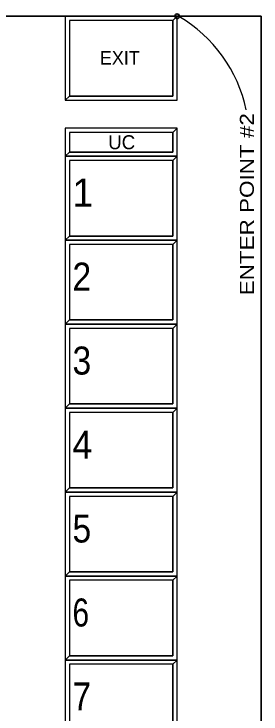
# Model space of a CAD drawing. Extents: x 95906.8 to 95923.6, y 90964.8 to 90972.8.
# Drawn here: x 95917.949 to 95918.832, y 90970.269 to 90972.77 of the extents above; entities that cross this region are included whole.
import ezdxf
from ezdxf.enums import TextEntityAlignment as Align

# ---------------------------------------------------------------- set-up
doc = ezdxf.new("R2010")
doc.units = 0
doc.header["$LTSCALE"] = 0.019
for name, color, linetype, lineweight in [('1', 7, 'Continuous', 25), ('11', 7, 'Continuous', 25), ('16', 7, 'Continuous', 25), ('18', 7, 'Continuous', 25), ('2', 7, 'Continuous', 13), ('3', 7, 'Continuous', 25), ('6', 7, 'Continuous', 35), ('7', 7, 'Continuous', 35)]:
    doc.layers.add(name, color=color, linetype=linetype, lineweight=lineweight)

msp = doc.modelspace()

# ---------------------------------------------------------------- linework, layer by layer
at = {"layer": '1'}
for points in [[(95918.1323, 90972.4617), (95918.5323, 90972.4617), (95918.5323, 90972.7617), (95918.1323, 90972.7617)], [(95918.1323, 90972.2617), (95918.5323, 90972.2617), (95918.5323, 90972.3617), (95918.1323, 90972.3617)], [(95918.1323, 90971.9617), (95918.5323, 90971.9617), (95918.5323, 90972.2617), (95918.1323, 90972.2617)], [(95918.1323, 90971.6617), (95918.5323, 90971.6617), (95918.5323, 90971.9617), (95918.1323, 90971.9617)], [(95918.1323, 90971.3617), (95918.5323, 90971.3617), (95918.5323, 90971.6617), (95918.1323, 90971.6617)], [(95918.1323, 90971.0617), (95918.5323, 90971.0617), (95918.5323, 90971.3617), (95918.1323, 90971.3617)], [(95918.1323, 90970.7617), (95918.5323, 90970.7617), (95918.5323, 90971.0617), (95918.1323, 90971.0617)], [(95918.1323, 90970.4617), (95918.5323, 90970.4617), (95918.5323, 90970.7617), (95918.1323, 90970.7617)], [(95918.1323, 90970.1617), (95918.5323, 90970.1617), (95918.5323, 90970.4617), (95918.1323, 90970.4617)]]:
    msp.add_lwpolyline(points, close=True, dxfattribs=at)
at = {"layer": '11'}
for points in [[(95918.1473, 90971.9767), (95918.5173, 90971.9767), (95918.5173, 90972.2467), (95918.1473, 90972.2467)], [(95918.1473, 90971.6767), (95918.5173, 90971.6767), (95918.5173, 90971.9467), (95918.1473, 90971.9467)], [(95918.1473, 90971.3767), (95918.5173, 90971.3767), (95918.5173, 90971.6467), (95918.1473, 90971.6467)], [(95918.1473, 90971.0767), (95918.5173, 90971.0767), (95918.5173, 90971.3467), (95918.1473, 90971.3467)], [(95918.1473, 90970.7767), (95918.5173, 90970.7767), (95918.5173, 90971.0467), (95918.1473, 90971.0467)], [(95918.1473, 90970.4767), (95918.5173, 90970.4767), (95918.5173, 90970.7467), (95918.1473, 90970.7467)], [(95918.1473, 90970.1767), (95918.5173, 90970.1767), (95918.5173, 90970.4467), (95918.1473, 90970.4467)]]:
    msp.add_lwpolyline(points, close=True, dxfattribs=at)
at = {"layer": '16'}
msp.add_lwpolyline([(95918.1473, 90972.4767), (95918.5173, 90972.4767), (95918.5173, 90972.7467), (95918.1473, 90972.7467)], close=True, dxfattribs=at)
msp.add_lwpolyline([(95918.1473, 90972.4767), (95918.5173, 90972.4767), (95918.5173, 90972.7467), (95918.1473, 90972.7467)], close=True, dxfattribs=at)
at = {"layer": '18'}
msp.add_lwpolyline([(95918.1473, 90972.2767), (95918.5173, 90972.2767), (95918.5173, 90972.3467), (95918.1473, 90972.3467)], close=True, dxfattribs=at)
at = {"layer": '2'}
for points in [[(95918.1323, 90972.7617), (95918.1323, 90972.4617), (95918.1473, 90972.4767), (95918.1473, 90972.7467), (95918.5173, 90972.7467), (95918.5323, 90972.7617)], [(95918.1323, 90972.3617), (95918.1323, 90972.2617), (95918.1473, 90972.2767), (95918.1473, 90972.3467), (95918.5173, 90972.3467), (95918.5323, 90972.3617)], [(95918.1323, 90972.2617), (95918.1323, 90971.9617), (95918.1473, 90971.9767), (95918.1473, 90972.2467), (95918.5173, 90972.2467), (95918.5323, 90972.2617)], [(95918.1323, 90971.9617), (95918.1323, 90971.6617), (95918.1473, 90971.6767), (95918.1473, 90971.9467), (95918.5173, 90971.9467), (95918.5323, 90971.9617)], [(95918.1323, 90971.6617), (95918.1323, 90971.3617), (95918.1473, 90971.3767), (95918.1473, 90971.6467), (95918.5173, 90971.6467), (95918.5323, 90971.6617)], [(95918.1323, 90971.3617), (95918.1323, 90971.0617), (95918.1473, 90971.0767), (95918.1473, 90971.3467), (95918.5173, 90971.3467), (95918.5323, 90971.3617)], [(95918.1323, 90971.0617), (95918.1323, 90970.7617), (95918.1473, 90970.7767), (95918.1473, 90971.0467), (95918.5173, 90971.0467), (95918.5323, 90971.0617)], [(95918.1323, 90970.7617), (95918.1323, 90970.4617), (95918.1473, 90970.4767), (95918.1473, 90970.7467), (95918.5173, 90970.7467), (95918.5323, 90970.7617)], [(95918.1323, 90970.4617), (95918.1323, 90970.1617), (95918.1473, 90970.1767), (95918.1473, 90970.4467), (95918.5173, 90970.4467), (95918.5323, 90970.4617)]]:
    msp.add_lwpolyline(points, close=True, dxfattribs=at)
at = {"layer": '3'}
for points in [[(95918.1323, 90972.4617), (95918.5323, 90972.4617), (95918.5323, 90972.7617), (95918.5173, 90972.7467), (95918.5173, 90972.4767), (95918.1473, 90972.4767)], [(95918.1323, 90972.2617), (95918.5323, 90972.2617), (95918.5323, 90972.3617), (95918.5173, 90972.3467), (95918.5173, 90972.2767), (95918.1473, 90972.2767)], [(95918.1323, 90971.9617), (95918.5323, 90971.9617), (95918.5323, 90972.2617), (95918.5173, 90972.2467), (95918.5173, 90971.9767), (95918.1473, 90971.9767)], [(95918.1323, 90971.6617), (95918.5323, 90971.6617), (95918.5323, 90971.9617), (95918.5173, 90971.9467), (95918.5173, 90971.6767), (95918.1473, 90971.6767)], [(95918.1323, 90971.3617), (95918.5323, 90971.3617), (95918.5323, 90971.6617), (95918.5173, 90971.6467), (95918.5173, 90971.3767), (95918.1473, 90971.3767)], [(95918.1323, 90971.0617), (95918.5323, 90971.0617), (95918.5323, 90971.3617), (95918.5173, 90971.3467), (95918.5173, 90971.0767), (95918.1473, 90971.0767)], [(95918.1323, 90970.7617), (95918.5323, 90970.7617), (95918.5323, 90971.0617), (95918.5173, 90971.0467), (95918.5173, 90970.7767), (95918.1473, 90970.7767)], [(95918.1323, 90970.4617), (95918.5323, 90970.4617), (95918.5323, 90970.7617), (95918.5173, 90970.7467), (95918.5173, 90970.4767), (95918.1473, 90970.4767)], [(95918.1323, 90970.1617), (95918.5323, 90970.1617), (95918.5323, 90970.4617), (95918.5173, 90970.4467), (95918.5173, 90970.1767), (95918.1473, 90970.1767)]]:
    msp.add_lwpolyline(points, close=True, dxfattribs=at)
at = {"layer": '7'}
msp.add_lwpolyline([(95906.8323, 90972.7617), (95918.8323, 90972.7617), (95918.8323, 90964.7617), (95906.8323, 90964.7617)], close=True, dxfattribs=at)
msp.add_circle((95918.5323, 90972.7617), 0.00808, dxfattribs=at)
at = {"layer": '7', "lineweight": 25}
msp.add_arc((95918.2789, 90972.3194), 0.5123, 12.1659, 59.4893, dxfattribs=at)

# ---------------------------------------------------------------- texts
at = {"layer": '6'}
msp.add_text('EXIT', height=0.048, dxfattribs=at).set_placement((95918.3275, 90972.5893), align=Align.CENTER)
msp.add_text('1', height=0.1, dxfattribs=at).set_placement((95918.1581, 90972.0818))
for s, width, p in [('2', 0.9, (95918.1581, 90971.7818)), ('3', 0.9, (95918.1581, 90971.4818)), ('4', 0.95, (95918.1581, 90971.1818)), ('5', 0.9, (95918.1581, 90970.8818)), ('6', 0.8, (95918.1581, 90970.5818)), ('7', 0.9, (95918.1581, 90970.2818))]:
    msp.add_text(s, height=0.1, dxfattribs=dict(at, width=width)).set_placement(p)
at = {"layer": '7', "width": 1.2}
msp.add_text('ENTER POINT #2', height=0.05, rotation=90, dxfattribs=at).set_placement((95918.8067, 90972.0903), align=Align.CENTER)
at = {"layer": '7'}
msp.add_text('UC', height=0.04999, dxfattribs=at).set_placement((95918.3341, 90972.2867), align=Align.CENTER)

doc.saveas('drawing.dxf')
